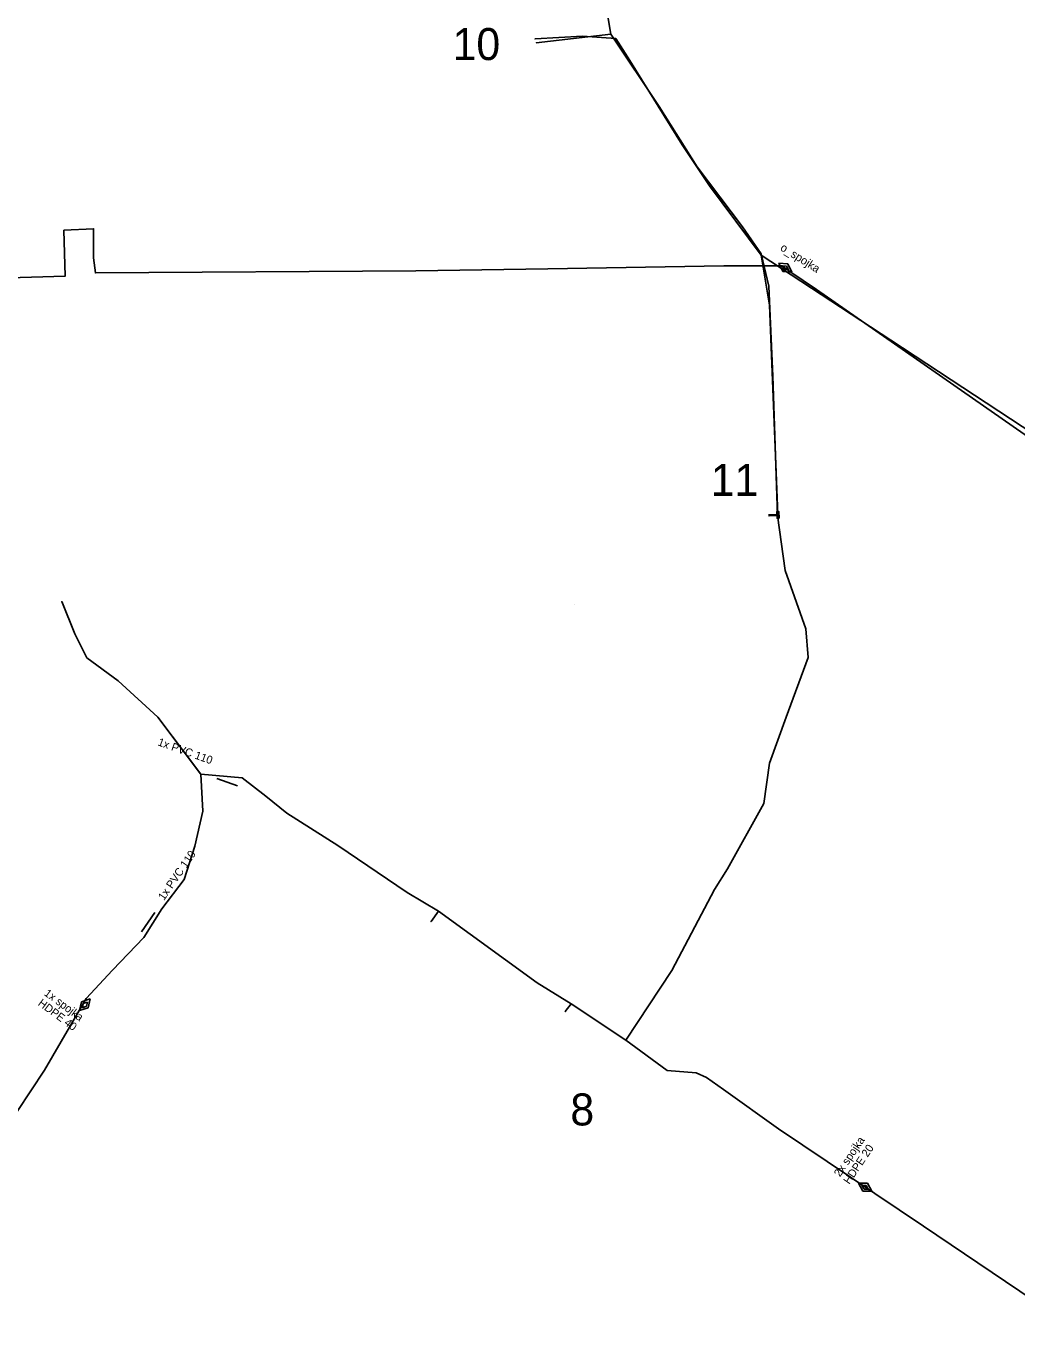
# Model space of a CAD drawing. Extents: x -651943 to -618711, y -1138561 to -1100552.
# Drawn here: x -641844.6 to -641751.7, y -1115558.2 to -1115436.2 of the extents above; entities that cross this region are included whole.
import ezdxf

# ---------------------------------------------------------------- set-up
doc = ezdxf.new("R2010")
doc.units = 0
for name, color, linetype in [('KT optika', 7, 'Continuous'), ('KT trasa', 7, 'Continuous'), ('KT zařízení', 7, 'Continuous'), ('SATT bloky', 7, 'Continuous'), ('SATT stanice', 7, 'Continuous')]:
    doc.layers.add(name, color=color, linetype=linetype)

# ---------------------------------------------------------------- blocks, each defined once
blk = doc.blocks.new('POINT_DISPLAY')
blk.add_line((0, 0), (0, 0))
blk = doc.blocks.new('TVSPO_1')
at = {"layer": 'KT zařízení'}
for p, q in [((-0.074, 0.002), (0, 0.044)), ((-0.001, -0.041), (-0.074, 0.002)), ((-0.035, 0), (0, 0.02)), ((0.073, 0.001), (-0.001, -0.041)), ((0, 0.044), (0.073, 0.001)), ((0, 0.02), (0.035, 0)), ((0.035, 0), (0, -0.02)), ((0, -0.02), (-0.035, 0))]:
    blk.add_line(p, q, dxfattribs=at)

msp = doc.modelspace()

# ---------------------------------------------------------------- linework, layer by layer
at = {"layer": 'KT optika'}
for points in [[(-641775.01, -1115482.04), (-641774.14, -1115482), (-641774.14, -1115482), (-641774.9, -1115462.38), (-641775.69, -1115457.7), (-641780.54, -1115451.2), (-641783.11, -1115447.35), (-641788, -1115439.46), (-641789.33, -1115437.41), (-641792.43, -1115437.19), (-641796.89, -1115437.44), (-641792.43, -1115437.19)], [(-641774.17, -1115482.06), (-641774.6, -1115469.06), (-641774.97, -1115460.6), (-641775.68, -1115457.59), (-641777.43, -1115455.05), (-641781.7, -1115449.43), (-641785.27, -1115443.76), (-641789.78, -1115436.99), (-641796.77, -1115437.79), (-641789.78, -1115436.99), (-641785.27, -1115443.76), (-641781.7, -1115449.43), (-641777.43, -1115455.05), (-641775.68, -1115457.59), (-641774.97, -1115460.6), (-641774.6, -1115469.06), (-641774.17, -1115482.1)], [(-641750.33, -1115474.97), (-641770.5, -1115460.93), (-641773.02, -1115459.24), (-641773.73, -1115458.71), (-641779.18, -1115458.7), (-641795.7, -1115459), (-641808.08, -1115459.18), (-641838.11, -1115459.37), (-641838.27, -1115457.95), (-641838.28, -1115455.23), (-641841.05, -1115455.37), (-641840.93, -1115459.67), (-641853.61, -1115460.06)], [(-641774.17, -1115482.1), (-641773.45, -1115487.26), (-641771.51, -1115492.73), (-641771.29, -1115495.4), (-641773.36, -1115501.02), (-641774.9, -1115505.31), (-641775.44, -1115509.09), (-641778.85, -1115515.23), (-641780.08, -1115517.16), (-641784.06, -1115524.75), (-641788.37, -1115531.28)], [(-641774.17, -1115482.1), (-641774.95, -1115482.14), (-641774.17, -1115482.1)], [(-641828.24, -1115506.32), (-641832.26, -1115501.01), (-641835.98, -1115497.59), (-641838.9, -1115495.44), (-641840.05, -1115493.18), (-641841.26, -1115490.17), (-641840.05, -1115493.18), (-641838.9, -1115495.44), (-641835.98, -1115497.59), (-641832.26, -1115501.01), (-641828.21, -1115506.35)], [(-641828.21, -1115506.35), (-641828.04, -1115509.83), (-641828.77, -1115513.11), (-641829.77, -1115516.21), (-641831.88, -1115518.98), (-641833.58, -1115521.65), (-641836.49, -1115524.71), (-641838.98, -1115527.37), (-641842.89, -1115534.09), (-641845.45, -1115537.95), (-641847.79, -1115540.38), (-641849.47, -1115539.62), (-641851.58, -1115541.81), (-641853.05, -1115543.86)], [(-641828.21, -1115506.35), (-641824.36, -1115506.7), (-641822.13, -1115508.42), (-641820.16, -1115509.99), (-641815.39, -1115513.02), (-641808.88, -1115517.43), (-641805.95, -1115519.2)], [(-641805.95, -1115519.2), (-641806.64, -1115520.16), (-641805.95, -1115519.2)], [(-641793.51, -1115527.87), (-641796.68, -1115525.91), (-641805.95, -1115519.2)], [(-641793.51, -1115527.87), (-641794.06, -1115528.6), (-641793.51, -1115527.87)], [(-641788.37, -1115531.28), (-641788.37, -1115531.28), (-641793.51, -1115527.87)], [(-641788.37, -1115531.28), (-641784.5, -1115534.13), (-641781.79, -1115534.33), (-641780.82, -1115534.77), (-641779.23, -1115535.9), (-641774.07, -1115539.6), (-641760.46, -1115548.72), (-641746.34, -1115558.25)]]:
    msp.add_lwpolyline(points, dxfattribs=at)
at = {"layer": 'KT trasa'}
for p, q in [((-641789.78, -1115436.99), (-641790.09, -1115435.15)), ((-641792.43, -1115437.19), (-641796.89, -1115437.44)), ((-641792.43, -1115437.19), (-641789.33, -1115437.41)), ((-641789.33, -1115437.41), (-641788, -1115439.46)), ((-641788, -1115439.46), (-641783.11, -1115447.35)), ((-641783.11, -1115447.35), (-641780.54, -1115451.2)), ((-641780.54, -1115451.2), (-641775.69, -1115457.7)), ((-641775.69, -1115457.7), (-641763.53, -1115465.68)), ((-641775.69, -1115457.7), (-641774.9, -1115462.38)), ((-641774.9, -1115462.38), (-641774.14, -1115482)), ((-641763.53, -1115465.68), (-641745.84, -1115477.3)), ((-641774.14, -1115482), (-641775.01, -1115482.04))]:
    msp.add_line(p, q, dxfattribs=at)
for points in [[(-641774.17, -1115482.06), (-641774.6, -1115469.06), (-641774.97, -1115460.6), (-641775.68, -1115457.59), (-641777.43, -1115455.05), (-641781.7, -1115449.43), (-641785.27, -1115443.76), (-641789.78, -1115436.99), (-641796.77, -1115437.79), (-641789.78, -1115436.99), (-641785.27, -1115443.76), (-641781.7, -1115449.43), (-641777.43, -1115455.05), (-641775.68, -1115457.59), (-641774.97, -1115460.6), (-641774.6, -1115469.06), (-641774.17, -1115482.1)], [(-641750.33, -1115474.97), (-641770.5, -1115460.93), (-641773.02, -1115459.24), (-641773.73, -1115458.71), (-641779.18, -1115458.7), (-641795.7, -1115459), (-641808.08, -1115459.18), (-641838.11, -1115459.37), (-641838.27, -1115457.95), (-641838.28, -1115455.23), (-641841.05, -1115455.37), (-641840.93, -1115459.67), (-641853.61, -1115460.06)], [(-641774.17, -1115482.1), (-641773.45, -1115487.26), (-641771.51, -1115492.73), (-641771.29, -1115495.4), (-641773.36, -1115501.02), (-641774.9, -1115505.31), (-641775.44, -1115509.09), (-641778.85, -1115515.23), (-641780.08, -1115517.16), (-641784.06, -1115524.75), (-641788.37, -1115531.28)], [(-641774.17, -1115482.1), (-641774.95, -1115482.14), (-641774.17, -1115482.1)], [(-641828.24, -1115506.32), (-641832.26, -1115501.01), (-641835.98, -1115497.59), (-641838.9, -1115495.44), (-641840.05, -1115493.18), (-641841.26, -1115490.17), (-641840.05, -1115493.18), (-641838.9, -1115495.44), (-641835.98, -1115497.59), (-641832.26, -1115501.01), (-641828.21, -1115506.35)], [(-641828.21, -1115506.35), (-641828.04, -1115509.83), (-641828.77, -1115513.11), (-641829.77, -1115516.21), (-641831.88, -1115518.98), (-641833.58, -1115521.65), (-641836.49, -1115524.71), (-641838.98, -1115527.37), (-641842.89, -1115534.09), (-641845.45, -1115537.95), (-641847.79, -1115540.38), (-641849.47, -1115539.62), (-641851.58, -1115541.81), (-641853.05, -1115543.86)], [(-641828.21, -1115506.35), (-641824.36, -1115506.7), (-641822.13, -1115508.42), (-641820.16, -1115509.99), (-641815.39, -1115513.02), (-641808.88, -1115517.43), (-641805.95, -1115519.2)], [(-641805.95, -1115519.2), (-641806.64, -1115520.16), (-641805.95, -1115519.2)], [(-641793.51, -1115527.87), (-641796.68, -1115525.91), (-641805.95, -1115519.2)], [(-641793.51, -1115527.87), (-641794.06, -1115528.6), (-641793.51, -1115527.87)], [(-641788.37, -1115531.28), (-641788.37, -1115531.28), (-641793.51, -1115527.87)], [(-641788.37, -1115531.28), (-641784.5, -1115534.13), (-641781.79, -1115534.33), (-641780.82, -1115534.77), (-641779.23, -1115535.9), (-641774.07, -1115539.6), (-641760.46, -1115548.72), (-641746.34, -1115558.25)]]:
    msp.add_lwpolyline(points, dxfattribs=at)
at = {"layer": 'KT zařízení'}
for p, q in [((-641824.78, -1115507.45), (-641826.71, -1115506.76)), ((-641832.55, -1115519.31), (-641833.8, -1115521.13))]:
    msp.add_line(p, q, dxfattribs=at)
msp.add_lwpolyline([(-641774, -1115482.35), (-641774.03, -1115481.75), (-641774.23, -1115481.76), (-641774.2, -1115482.36)], close=True, dxfattribs=at)

# ---------------------------------------------------------------- block references
for p, xscale, yscale, rotation in [((-641773.43, -1115458.89), 10.000001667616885, 10.000001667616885, -34.007089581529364), ((-641839.09, -1115527.97), 10.000006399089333, 10.000006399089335, 48.36214006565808), ((-641765.95, -1115545.07), 10.000012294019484, 10.000012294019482, -30.58891599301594)]:
    msp.add_blockref('TVSPO_1', p, dxfattribs=dict(at, xscale=xscale, yscale=yscale, rotation=rotation))
at = {"layer": 'SATT stanice'}
msp.add_blockref('POINT_DISPLAY', (-641793.18, -1115490.44), dxfattribs=at)

# ---------------------------------------------------------------- texts
at = {"layer": 'KT zařízení'}
for s, height, rotation, p in [('o_spojka', 0.77, 327.8135, (-641773.97, -1115457.19)), ('1x PVC 110', 0.75, 340.3274, (-641832.32, -1115503.63)), ('1x PVC 110', 0.75, 55.5182, (-641831.68, -1115518.24)), ('HDPE 40', 0.75, 323.3768, (-641843.55, -1115527.95)), ('1x spojka', 0.75, 323.3768, (-641842.98, -1115527.01)), ('2x spojka', 0.75, 56.0596, (-641768.31, -1115544.15)), ('HDPE 20', 0.75, 56.0596, (-641767.43, -1115544.84))]:
    msp.add_text(s, height=height, rotation=rotation, dxfattribs=at).set_placement(p)
at = {"layer": 'SATT bloky'}
for s, p in [('10', (-641804.62, -1115439.42)), ('11', (-641780.42, -1115480.27)), ('8', (-641793.58, -1115539.27))]:
    msp.add_text(s, height=3, dxfattribs=at).set_placement(p)

doc.saveas('drawing.dxf')
